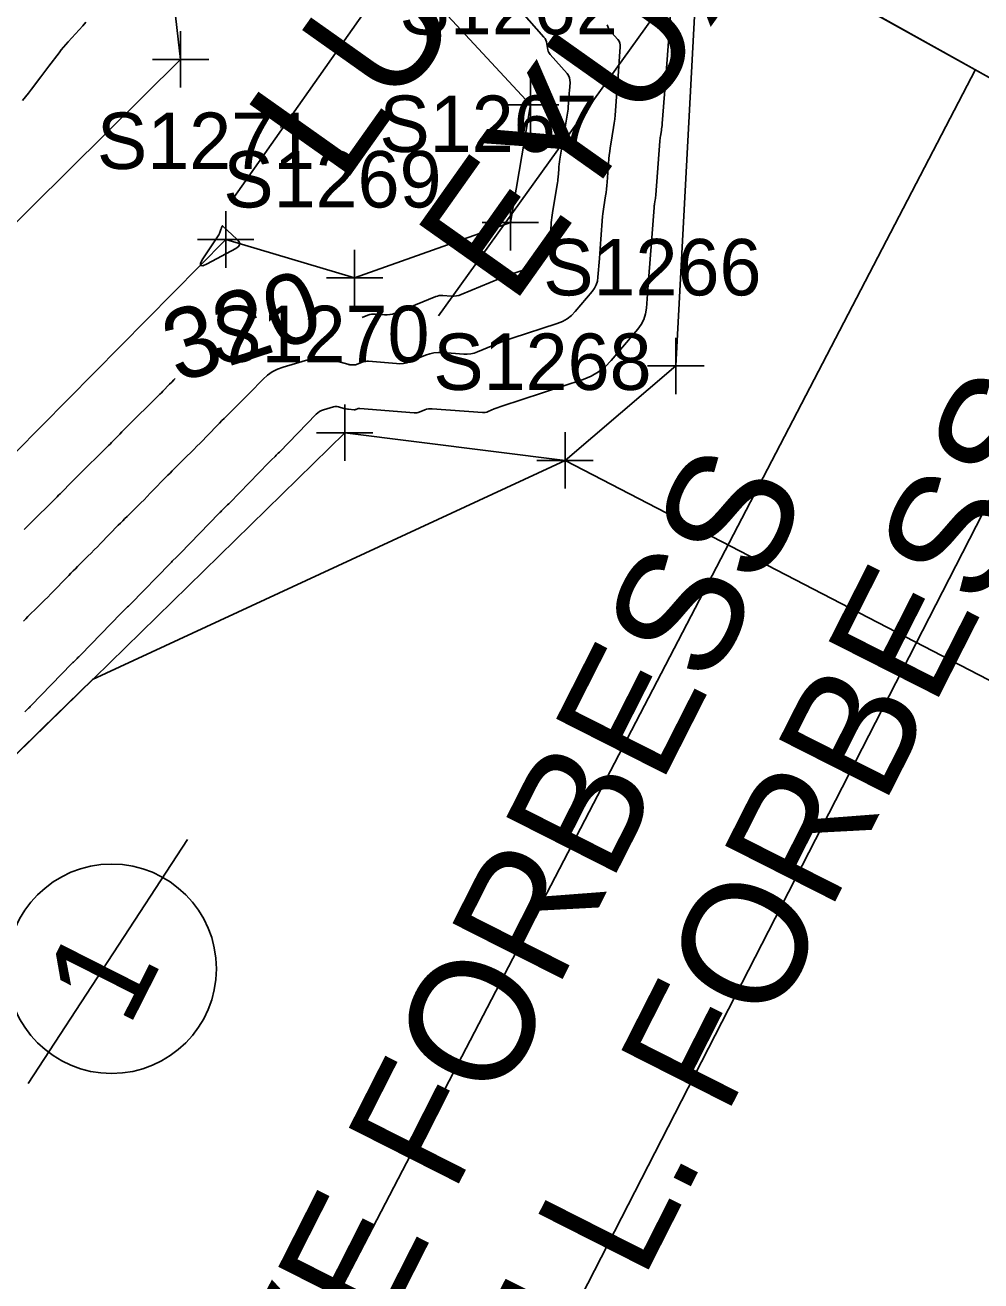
# Model space of a CAD drawing. Extents: x 816928 to 825690, y 436959 to 448212.
# Drawn here: x 818845.8 to 818913.6, y 444413.7 to 444502.7 of the extents above; entities that cross this region are included whole.
import ezdxf

# ---------------------------------------------------------------- set-up
doc = ezdxf.new("R2010")
doc.units = 0
for name, color, linetype in [('DESIGN - SCRATCH - User 1', 7, 'Continuous'), ('SURVEY - CONTOURS - Index with Text', 7, 'Continuous'), ('SURVEY - CONTOURS - Intermediate with optional Text', 7, 'Continuous'), ('SURVEY - DTM - Breaklines', 7, 'Continuous'), ('SURVEY - DTM - Breaklines - Points - Locators', 7, 'Continuous'), ('SURVEY - DTM - Breaklines - Points - Numbers', 7, 'Continuous'), ('SURVEY - PROPERTY - Owners', 7, 'Continuous'), ('SURVEY - PROPERTY - Parcels', 7, 'Continuous'), ('SURVEY - PROPERTY - Property Lines', 7, 'Continuous'), ('SURVEY - PROPERTY - Tract Numbers', 7, 'Continuous')]:
    doc.layers.add(name, color=color, linetype=linetype)

msp = doc.modelspace()

# ---------------------------------------------------------------- linework, layer by layer
at = {"layer": 'DESIGN - SCRATCH - User 1'}
msp.add_lwpolyline([(818640.147, 444520.892), (818676.038, 444463.993), (818725.201, 444432.827), (818735.804, 444428.835), (818765.207, 444431.593), (818770.156, 444432.208), (818775.104, 444432.822), (818780.053, 444433.437), (818785.002, 444434.051), (818789.95, 444434.665), (818789.97, 444434.668), (818836.244, 444442.278), (818836.31, 444442.343), (818839.883, 444445.84), (818843.456, 444449.337), (818847.029, 444452.835), (818850.602, 444456.332), (818884.078, 444471.852), (818940.13, 444442.798), (818943.136, 444492.177), (818941.02, 444542.4)], dxfattribs=at)
at = {"layer": 'SURVEY - CONTOURS - Index with Text'}
for points in [[(818880.494, 444504.226), (818882.578, 444501.869), (818882.66, 444501.762), (818882.724, 444501.648), (818882.771, 444501.525), (818882.801, 444501.394), (818882.868, 444500.954), (818882.889, 444500.862), (818882.922, 444500.776), (818882.967, 444500.696), (818883.024, 444500.622), (818884.219, 444499.278), (818884.323, 444499.137), (818884.394, 444498.984), (818884.431, 444498.819), (818884.434, 444498.644), (818884.39, 444498.051), (818884.38, 444497.924), (818884.371, 444497.797), (818884.361, 444497.67), (818884.352, 444497.543), (818884.303, 444496.889), (818884.291, 444496.75), (818884.276, 444496.61), (818884.257, 444496.471), (818884.236, 444496.333), (818883.715, 444493.203), (818883.688, 444493.027), (818883.664, 444492.851), (818883.645, 444492.674), (818883.63, 444492.496), (818883.586, 444491.916), (818883.575, 444491.792), (818883.562, 444491.668), (818883.545, 444491.544), (818883.526, 444491.421), (818883.193, 444489.417), (818883.166, 444489.243), (818883.143, 444489.067), (818883.123, 444488.892), (818883.108, 444488.716), (818883.064, 444488.139), (818883.055, 444488.016), (818883.046, 444487.893), (818883.036, 444487.769), (818883.027, 444487.646), (818882.979, 444487.01), (818882.958, 444486.878), (818882.919, 444486.754), (818882.86, 444486.637), (818882.781, 444486.529), (818882.255, 444485.907), (818882.135, 444485.784), (818882.002, 444485.68), (818881.856, 444485.596), (818881.697, 444485.532), (818880.478, 444485.131), (818880.218, 444485.043), (818879.96, 444484.95), (818879.703, 444484.852), (818879.448, 444484.749), (818876.727, 444483.616), (818876.555, 444483.556), (818876.38, 444483.517), (818876.202, 444483.499), (818876.021, 444483.502), (818875.422, 444483.546), (818875.295, 444483.548), (818875.17, 444483.536), (818875.048, 444483.509), (818874.927, 444483.468), (818872.042, 444482.293), (818871.858, 444482.23), (818871.67, 444482.19), (818871.479, 444482.172), (818871.284, 444482.177), (818870.641, 444482.229), (818870.505, 444482.233), (818870.371, 444482.221), (818870.239, 444482.193), (818870.11, 444482.15), (818869.7, 444481.987)], [(818845.62, 444497.376), (818845.841, 444497.633), (818846.055, 444497.896), (818846.263, 444498.164), (818846.932, 444499.048), (818847.075, 444499.238), (818847.219, 444499.427), (818847.362, 444499.617), (818847.505, 444499.806), (818848.223, 444500.755), (818848.379, 444500.957), (818848.54, 444501.154), (818848.706, 444501.347), (818848.876, 444501.537), (818849.915, 444502.665), (818850.115, 444502.917)], [(818856.458, 444477.665), (818856.355, 444477.562), (818856.206, 444477.411), (818856.057, 444477.259), (818855.573, 444476.762), (818855.469, 444476.656), (818855.365, 444476.55), (818855.26, 444476.445), (818855.154, 444476.34), (818853.119, 444474.326), (818852.969, 444474.176), (818852.819, 444474.026), (818852.67, 444473.875), (818852.522, 444473.724), (818852.039, 444473.228), (818851.935, 444473.122), (818851.831, 444473.017), (818851.726, 444472.911), (818851.621, 444472.807), (818849.583, 444470.79), (818849.432, 444470.64), (818849.283, 444470.491), (818849.134, 444470.34), (818848.987, 444470.189), (818848.504, 444469.694), (818848.401, 444469.588), (818848.297, 444469.483), (818848.192, 444469.378), (818848.087, 444469.273), (818846.046, 444467.253), (818845.896, 444467.105), (818845.747, 444466.955)]]:
    msp.add_lwpolyline(points, dxfattribs=at)
at = {"layer": 'SURVEY - CONTOURS - Intermediate with optional Text'}
for points in [[(818891.571, 444503.824), (818891.354, 444500.912), (818891.307, 444500.287), (818891.261, 444499.663), (818891.214, 444499.039), (818891.168, 444498.415), (818890.968, 444495.733), (818890.957, 444495.608), (818890.943, 444495.483), (818890.927, 444495.359), (818890.908, 444495.236), (818890.841, 444494.832), (818890.827, 444494.745), (818890.816, 444494.658), (818890.806, 444494.571), (818890.799, 444494.484), (818890.513, 444490.695), (818890.505, 444490.605), (818890.495, 444490.516), (818890.483, 444490.426), (818890.47, 444490.337), (818890.421, 444490.046), (818890.412, 444489.983), (818890.403, 444489.921), (818890.396, 444489.858), (818890.391, 444489.795), (818890.18, 444487.017), (818890.135, 444486.421), (818890.089, 444485.826), (818890.044, 444485.23), (818889.999, 444484.635), (818889.848, 444482.653), (818889.786, 444482.241), (818889.662, 444481.854), (818889.478, 444481.491), (818889.233, 444481.154), (818887.354, 444478.935), (818886.927, 444478.494), (818886.454, 444478.124), (818885.933, 444477.824), (818885.364, 444477.595), (818879.606, 444475.703), (818879.468, 444475.656), (818879.331, 444475.606), (818879.195, 444475.554), (818879.06, 444475.5), (818878.621, 444475.317), (818878.526, 444475.284), (818878.429, 444475.262), (818878.33, 444475.252), (818878.229, 444475.254), (818874.656, 444475.516), (818874.526, 444475.519), (818874.398, 444475.506), (818874.273, 444475.479), (818874.15, 444475.437), (818873.752, 444475.275), (818873.666, 444475.245), (818873.579, 444475.226), (818873.489, 444475.218), (818873.398, 444475.22), (818869.531, 444475.537), (818869.49, 444475.538), (818869.45, 444475.535), (818869.411, 444475.527), (818869.373, 444475.514), (818869.248, 444475.464), (818869.221, 444475.455), (818869.194, 444475.449), (818869.166, 444475.447), (818869.137, 444475.448), (818868.743, 444475.481), (818868.659, 444475.49), (818868.576, 444475.503), (818868.493, 444475.52), (818868.411, 444475.541), (818868.016, 444475.651), (818867.931, 444475.669), (818867.847, 444475.674), (818867.763, 444475.667), (818867.678, 444475.649), (818866.968, 444475.439), (818866.821, 444475.386), (818866.684, 444475.315), (818866.558, 444475.227), (818866.442, 444475.122), (818863.835, 444472.448), (818863.759, 444472.371), (818863.683, 444472.294), (818863.606, 444472.217), (818863.529, 444472.14), (818863.277, 444471.891), (818863.223, 444471.837), (818863.17, 444471.783), (818863.116, 444471.729), (818863.063, 444471.675), (818860.314, 444468.855), (818860.241, 444468.78), (818860.168, 444468.706), (818860.095, 444468.633), (818860.021, 444468.559), (818859.779, 444468.32), (818859.728, 444468.269), (818859.676, 444468.217), (818859.625, 444468.165), (818859.574, 444468.113), (818856.793, 444465.26), (818856.724, 444465.189), (818856.654, 444465.118), (818856.584, 444465.048), (818856.513, 444464.977), (818856.282, 444464.749), (818856.233, 444464.7), (818856.184, 444464.65), (818856.135, 444464.601), (818856.086, 444464.551), (818853.273, 444461.664), (818853.207, 444461.596), (818853.14, 444461.529), (818853.073, 444461.461), (818853.006, 444461.395), (818852.786, 444461.177), (818852.739, 444461.13), (818852.692, 444461.083), (818852.646, 444461.036), (818852.599, 444460.988), (818849.753, 444458.066), (818849.69, 444458.002), (818849.627, 444457.938), (818849.563, 444457.874), (818849.5, 444457.811), (818849.291, 444457.604), (818849.246, 444457.56), (818849.202, 444457.515), (818849.157, 444457.47), (818849.113, 444457.425), (818846.233, 444454.467), (818846.174, 444454.406), (818846.114, 444454.346), (818846.054, 444454.286), (818845.994, 444454.226), (818845.796, 444454.03)], [(818887.063, 444502.735), (818887.136, 444502.545), (818887.236, 444502.367), (818887.363, 444502.203), (818887.823, 444501.686), (818887.907, 444501.571), (818887.965, 444501.446), (818887.995, 444501.312), (818887.998, 444501.169), (818887.87, 444499.462), (818887.843, 444499.096), (818887.816, 444498.73), (818887.788, 444498.364), (818887.761, 444497.998), (818887.659, 444496.632), (818887.634, 444496.339), (818887.602, 444496.048), (818887.564, 444495.757), (818887.519, 444495.467), (818887.32, 444494.269), (818887.28, 444494.012), (818887.246, 444493.754), (818887.217, 444493.495), (818887.195, 444493.236), (818887.07, 444491.575), (818887.049, 444491.334), (818887.022, 444491.093), (818886.991, 444490.852), (818886.954, 444490.612), (818886.823, 444489.83), (818886.797, 444489.662), (818886.775, 444489.494), (818886.757, 444489.325), (818886.742, 444489.156), (818886.62, 444487.548), (818886.594, 444487.204), (818886.567, 444486.859), (818886.541, 444486.515), (818886.515, 444486.17), (818886.414, 444484.841), (818886.372, 444484.564), (818886.289, 444484.304), (818886.166, 444484.061), (818886.001, 444483.835), (818884.802, 444482.419), (818884.53, 444482.138), (818884.228, 444481.902), (818883.896, 444481.711), (818883.533, 444481.564), (818880.332, 444480.512), (818879.988, 444480.396), (818879.647, 444480.273), (818879.309, 444480.143), (818878.973, 444480.007), (818877.879, 444479.552), (818877.642, 444479.469), (818877.401, 444479.415), (818877.154, 444479.39), (818876.904, 444479.394), (818875.417, 444479.503), (818875.101, 444479.509), (818874.791, 444479.478), (818874.487, 444479.412), (818874.188, 444479.309), (818873.097, 444478.865), (818872.861, 444478.784), (818872.62, 444478.733), (818872.376, 444478.71), (818872.126, 444478.716), (818870.14, 444478.879), (818870.025, 444478.882), (818869.912, 444478.872), (818869.8, 444478.848), (818869.691, 444478.812), (818869.299, 444478.656), (818869.241, 444478.636), (818869.182, 444478.624), (818869.122, 444478.619), (818869.061, 444478.62), (818868.86, 444478.637), (818868.817, 444478.642), (818868.775, 444478.649), (818868.733, 444478.657), (818868.691, 444478.668), (818867.284, 444479.06), (818866.983, 444479.123), (818866.682, 444479.142), (818866.382, 444479.118), (818866.081, 444479.051), (818864.095, 444478.465), (818863.7, 444478.322), (818863.332, 444478.132), (818862.993, 444477.896), (818862.681, 444477.613), (818861.708, 444476.616), (818861.5, 444476.402), (818861.29, 444476.19), (818861.079, 444475.979), (818860.867, 444475.768), (818860.093, 444475.002), (818859.928, 444474.837), (818859.763, 444474.672), (818859.599, 444474.506), (818859.436, 444474.339), (818858.215, 444473.087), (818857.991, 444472.858), (818857.765, 444472.63), (818857.539, 444472.402), (818857.311, 444472.176), (818856.566, 444471.439), (818856.407, 444471.28), (818856.248, 444471.121), (818856.09, 444470.961), (818855.933, 444470.801), (818854.688, 444469.523), (818854.465, 444469.295), (818854.241, 444469.069), (818854.016, 444468.843), (818853.79, 444468.618), (818853.05, 444467.885), (818852.891, 444467.728), (818852.734, 444467.57), (818852.577, 444467.411), (818852.421, 444467.252), (818851.161, 444465.958), (818850.94, 444465.732), (818850.717, 444465.507), (818850.494, 444465.283), (818850.269, 444465.059), (818849.534, 444464.332), (818849.377, 444464.175), (818849.22, 444464.018), (818849.064, 444463.861), (818848.909, 444463.702), (818847.634, 444462.393), (818847.414, 444462.168), (818847.193, 444461.945), (818846.971, 444461.722), (818846.748, 444461.5), (818846.018, 444460.778), (818845.862, 444460.623), (818845.707, 444460.467)], [(818859.619, 444488.022), (818859.689, 444488.224), (818859.7, 444488.257), (818859.711, 444488.289), (818859.722, 444488.322), (818859.733, 444488.354), (818859.77, 444488.46), (818859.779, 444488.478), (818859.79, 444488.486), (818859.804, 444488.484), (818859.821, 444488.473), (818860.831, 444487.546), (818860.988, 444487.355), (818861.026, 444487.179), (818860.945, 444487.019), (818860.745, 444486.874), (818858.724, 444485.801), (818858.4, 444485.66), (818858.241, 444485.669), (818858.246, 444485.829), (818858.415, 444486.139), (818859.538, 444487.858), (818859.562, 444487.897), (818859.584, 444487.937), (818859.602, 444487.979), (818859.619, 444488.022)]]:
    msp.add_lwpolyline(points, dxfattribs=at)
at = {"layer": 'SURVEY - DTM - Breaklines'}
for points in [[(818785.328, 444581.689), (818787.221, 444591.663), (818822.442, 444559.897), (818859.115, 444521.341), (818881.638, 444497.056), (818880.209, 444488.725), (818869.164, 444484.787), (818860.033, 444487.517), (818824.558, 444451.586)], [(818787.221, 444591.663), (818835.836, 444568.351), (818864.176, 444541.66), (818882.796, 444525.443), (818889.803, 444518.206), (818893.357, 444505.151), (818891.93, 444478.554), (818884.078, 444471.852), (818868.468, 444473.818), (818836.244, 444442.278)], [(818735.804, 444428.835), (818742.519, 444435.26), (818765.207, 444431.593), (818789.97, 444434.668), (818804.735, 444448.966), (818830.474, 444474.158), (818856.836, 444500.282), (818855.207, 444514.52), (818824.313, 444543.706), (818785.328, 444581.689)]]:
    msp.add_lwpolyline(points, dxfattribs=at)
at = {"layer": 'SURVEY - DTM - Breaklines - Points - Locators'}
for p, q in [((818856.836, 444502.282), (818856.836, 444498.282)), ((818858.836, 444500.282), (818854.836, 444500.282)), ((818881.638, 444499.056), (818881.638, 444495.056)), ((818883.638, 444497.056), (818879.638, 444497.056)), ((818880.209, 444490.725), (818880.209, 444486.725)), ((818860.033, 444489.517), (818860.033, 444485.517)), ((818882.209, 444488.725), (818878.209, 444488.725)), ((818862.033, 444487.517), (818858.033, 444487.517)), ((818869.164, 444486.787), (818869.164, 444482.787)), ((818871.164, 444484.787), (818867.164, 444484.787)), ((818891.93, 444480.554), (818891.93, 444476.554)), ((818893.93, 444478.554), (818889.93, 444478.554)), ((818868.468, 444475.818), (818868.468, 444471.818)), ((818870.468, 444473.818), (818866.468, 444473.818)), ((818884.078, 444473.852), (818884.078, 444469.852)), ((818886.078, 444471.852), (818882.078, 444471.852))]:
    msp.add_line(p, q, dxfattribs=at)
at = {"layer": 'SURVEY - PROPERTY - Owners'}
for p, q in [((818860.435, 444490.257), (818944.03, 444608.968)), ((818875.117, 444482.095), (818956.904, 444596.096)), ((818847.641, 444339.227), (818935.755, 444511.205)), ((818838.555, 444356.194), (818913.176, 444499.57)), ((818846.027, 444427.667), (818857.335, 444444.974))]:
    msp.add_line(p, q, dxfattribs=at)
at = {"layer": 'SURVEY - PROPERTY - Parcels'}
msp.add_line((819226.308, 444324.647), (818742.759, 444594.722), dxfattribs=at)
at = {"layer": 'SURVEY - PROPERTY - Property Lines'}
msp.add_line((818742.759, 444594.722), (819226.308, 444324.647), dxfattribs=at)
at = {"layer": 'SURVEY - PROPERTY - Tract Numbers'}
msp.add_circle((818851.948, 444435.81), 7.422, dxfattribs=at)

# ---------------------------------------------------------------- texts
at = {"layer": 'SURVEY - CONTOURS - Index with Text'}
msp.add_text('320', height=5, rotation=18.07478, dxfattribs=at).set_placement((818856.617, 444477.321))
at = {"layer": 'SURVEY - DTM - Breaklines - Points - Numbers'}
for s, p in [('S1262', (818872.35, 444502.056)), ('S1267', (818870.921, 444493.725)), ('S1271', (818850.903, 444492.517)), ('S1269', (818859.86, 444489.787)), ('S1266', (818882.532, 444483.554)), ('S1270', (818859.007, 444478.818)), ('S1268', (818874.743, 444476.852))]:
    msp.add_text(s, height=4, dxfattribs=at).set_placement(p)
at = {"layer": 'SURVEY - PROPERTY - Owners'}
for s, rotation, p in [('LUTHER F. BRYANT', 54.68153, (818868.303, 444491.264)), ('EYUX REBA BRYANT', 54.68153, (818880.338, 444482.736)), ('ETUX SUSAN L. FORBESS', 63.12559, (818854.303, 444344.036)), (' JOEL CLEVE FORBESS', 63.12559, (818841.147, 444350.704))]:
    msp.add_text(s, height=8.75, rotation=rotation, dxfattribs=at).set_placement(p)
at = {"layer": 'SURVEY - PROPERTY - Tract Numbers'}
msp.add_text('1', height=7, rotation=63.12559, dxfattribs=at).set_placement((818853.145, 444431.553))

doc.saveas('drawing.dxf')
